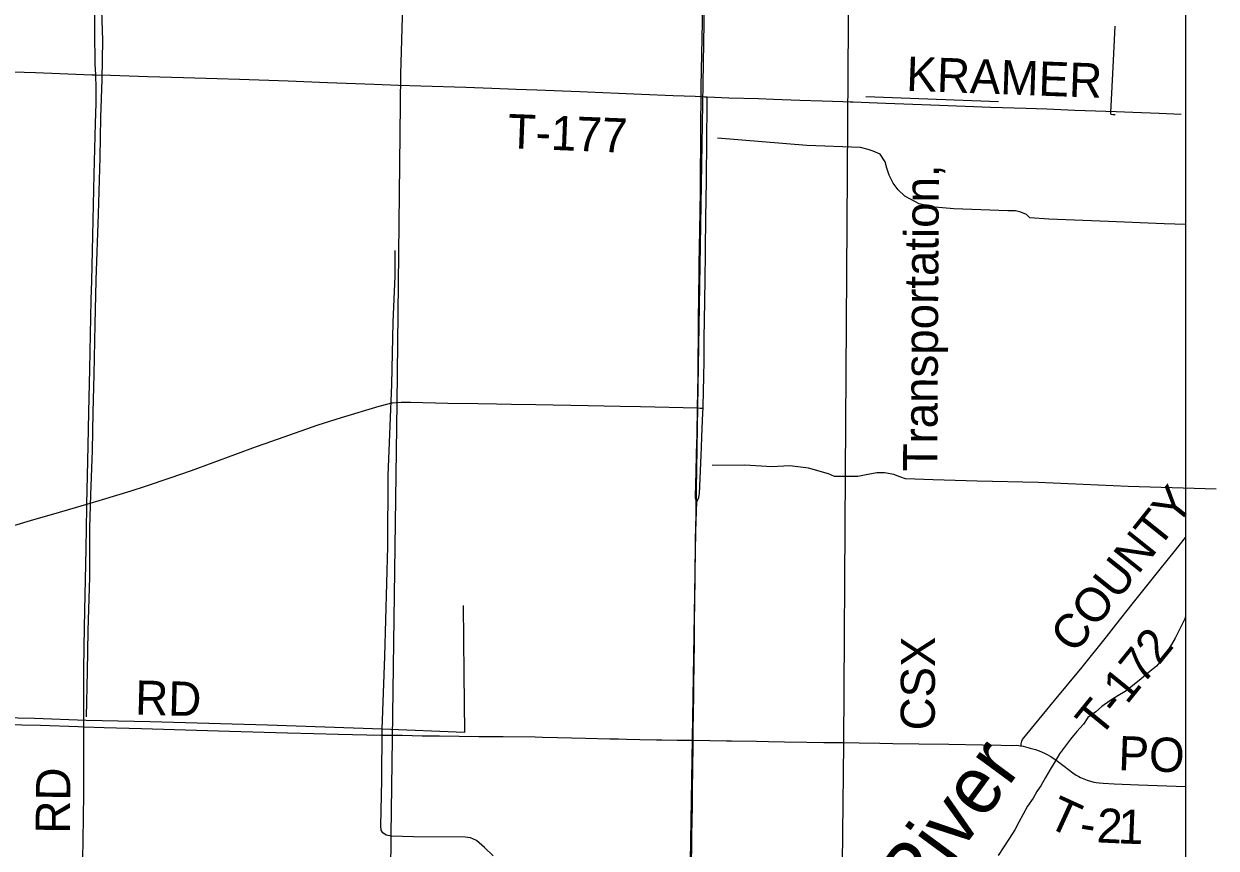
# Model space of a CAD drawing. Extents: x 0 to 680, y 0 to 834.
# Drawn here: x 300.6 to 376.6, y 223.2 to 275.7 of the extents above; entities that cross this region are included whole.
import ezdxf

# ---------------------------------------------------------------- set-up
doc = ezdxf.new("R2010")
doc.units = 0
for name, color, linetype in [('GM_X_Interstate_Route', 7, 'Continuous'), ('GM_X_Major_River', 7, 'Continuous'), ('GM_X_Minor_River', 7, 'Continuous'), ('GM_X_Minor_River_Text', 7, 'Continuous'), ('GM_X_Rail_Line', 7, 'Continuous'), ('GM_X_Rail_Line_Text', 7, 'Continuous'), ('GM_X_State_Route', 7, 'Continuous'), ('GM_X_Township_Road', 7, 'Continuous'), ('GM_X_Township_Road_Text', 7, 'Continuous')]:
    doc.layers.add(name, color=color, linetype=linetype)

msp = doc.modelspace()

# ---------------------------------------------------------------- linework, layer by layer
at = {"layer": 'GM_X_Interstate_Route'}
msp.add_lwpolyline([(44.693, 394.069), (374.693, 394.069), (374.693, 64.069), (44.693, 64.069)], close=True, dxfattribs=at)
at = {"layer": 'GM_X_Major_River'}
msp.add_lwpolyline([(374.693, 237.983), (374.631, 237.824), (374.411, 237.358), (374.22, 236.979), (374.015, 236.6), (373.795, 236.192), (373.502, 235.727), (373.268, 235.333), (372.844, 234.824), (372.304, 234.388), (371.851, 234.01), (371.31, 233.56), (370.843, 233.196), (370.376, 232.92), (369.85, 232.616), (369.339, 232.253), (368.974, 231.918), (368.463, 231.54), (368.17, 231.118), (367.746, 230.653), (367.351, 230.173), (366.971, 229.663), (366.649, 229.241), (366.356, 228.731), (366.063, 228.236), (365.756, 227.727), (365.462, 227.202), (365.199, 226.824), (364.965, 226.416), (364.613, 225.907), (364.335, 225.383), (364.056, 224.873), (363.793, 224.392), (363.471, 223.868), (363.105, 223.315), (362.739, 222.762)], dxfattribs=at)
at = {"layer": 'GM_X_Minor_River'}
for points in [[(305.442, 306.343), (305.457, 301.645), (305.341, 297.006), (305.374, 293.286), (305.384, 291.784), (305.402, 288.107), (305.459, 283.016), (305.518, 278.523), (305.638, 274.715), (305.601, 272.206), (305.506, 269.77), (305.455, 267.232), (305.357, 263.614), (305.213, 259.414), (305.146, 256.599), (305.078, 253.404), (305.027, 250.997), (304.976, 248.562), (304.88, 245.732), (304.8, 243.632), (304.805, 240.481), (304.707, 237.068), (304.655, 234.472), (304.603, 231.584)], [(362.755, 270.768), (354.305, 271.1)], [(374.693, 262.952), (373.324, 263.006), (369.784, 263.147), (365.967, 263.29), (364.758, 263.381), (364.554, 263.6), (364.191, 263.747), (363.841, 263.821), (363.36, 263.837), (359.922, 263.949), (358.702, 264.075), (357.709, 264.277), (356.792, 264.761), (356.356, 265.171), (356.052, 265.595), (355.791, 266.106), (355.632, 266.559), (355.531, 266.953), (355.212, 267.45), (354.776, 267.626), (354.441, 267.729), (353.961, 267.862), (350.537, 267.989), (344.856, 268.457)], [(328.75, 223.913), (325.458, 223.937), (324.059, 223.985), (323.724, 224.044), (323.506, 224.205), (323.405, 224.366), (323.376, 224.643), (323.444, 227.546), (323.468, 230.798), (323.629, 235.436), (323.825, 242.452), (323.853, 246.959), (323.98, 250.139), (324.075, 252.764), (324.16, 256.732), (324.286, 259.663), (324.291, 261.297)], [(376.638, 246.089), (371.029, 246.266), (365.289, 246.516), (361.399, 246.615), (358.587, 246.696), (356.839, 246.76), (356.461, 246.892), (356.097, 247.039), (355.5, 247.143), (355.005, 247.13), (354.319, 247), (353.795, 246.9), (353.052, 246.902), (352.308, 246.904), (351.916, 247.066), (350.649, 247.434), (349.455, 247.583), (348.304, 247.529), (346.585, 247.621), (344.501, 247.613)], [(328.622, 238.689), (328.666, 234.356), (328.713, 230.593), (323.468, 230.798), (316.155, 231.054), (308.681, 231.28), (304.588, 231.365), (301.295, 231.477), (296.079, 231.595), (294.448, 231.644), (284.73, 231.805), (279.515, 231.952), (273.848, 232.085), (267.511, 232.411), (265.69, 232.416)], [(330.553, 222.74), (329.987, 223.267), (329.478, 223.706), (329.108, 223.889), (328.75, 223.913)]]:
    msp.add_lwpolyline(points, dxfattribs=at)
at = {"layer": 'GM_X_Rail_Line'}
for points in [[(351.218, 64.069), (351.448, 90.121), (351.798, 116.184), (351.86, 139.423), (352.175, 154.252), (352.451, 189.912), (352.901, 229.863), (353.003, 247.107), (353.355, 298.069), (353.602, 311.675), (353.78, 316.856), (353.954, 319.076), (354.473, 323.516), (355.976, 338.772), (356.265, 341.847), (356.561, 344.985), (356.644, 347.076), (356.685, 349.146), (356.788, 357.395), (356.901, 372.817), (357.146, 391.252), (357.174, 394.069)], [(332.297, 358.476), (331.74, 334.991), (331.623, 332.119), (331.235, 330.489), (330.77, 329.441), (329.838, 328.432), (326.114, 325.676), (325.377, 324.318), (325.144, 323.27), (325.144, 290.084), (324.626, 272.539), (324.407, 251.582), (324.019, 224.102), (323.747, 191.887)], [(341.694, 64.069), (341.887, 75.733), (342.297, 152.995), (342.913, 209.384), (343.255, 230.188), (343.597, 251.334), (344.253, 291.298), (344.078, 319.736), (344.92, 358.256)]]:
    msp.add_lwpolyline(points, dxfattribs=at)
at = {"layer": 'GM_X_State_Route'}
msp.add_line((343.571, 251.27), (343.603, 253.33), dxfattribs=at)
for points in [[(343.805, 271.112), (343.813, 271.777), (343.881, 275.833), (343.936, 279.055), (343.938, 280.13), (343.944, 280.486), (343.969, 281.315), (343.992, 283.343), (343.995, 283.94), (344.039, 285.967), (344.048, 286.684), (344.048, 286.771)], [(343.603, 253.33), (343.606, 253.52), (343.609, 254.117), (343.637, 256.026), (343.628, 256.981), (343.658, 258.292), (343.676, 259.964), (343.685, 260.44), (343.723, 262.588), (343.752, 265.094), (343.783, 269.271), (343.805, 271.112)], [(343.977, 253.276), (343.996, 254.251), (344, 255.803), (344.019, 256.757), (344.04, 258.188), (344.052, 259.382), (344.074, 261.172), (344.11, 263.558), (344.127, 264.393), (344.134, 265.944), (344.188, 270.598), (344.195, 271.095)], [(343.914, 250.989), (343.926, 251.262), (343.93, 251.358), (343.977, 253.276)], [(343.533, 245.307), (343.599, 245.408), (343.658, 245.569), (343.682, 245.707), (343.693, 245.807), (343.822, 248.745), (343.844, 249.432), (343.914, 250.989)], [(343.543, 249.42), (343.546, 249.628), (343.571, 251.27)], [(343.533, 245.307), (343.473, 245.444), (343.45, 245.551), (343.439, 245.695), (343.464, 246.355), (343.536, 249.146), (343.543, 249.42)], [(343.377, 236.705), (343.385, 237.901), (343.389, 238.086), (343.397, 238.497), (343.407, 239.389), (343.413, 239.967), (343.417, 240.408), (343.427, 241.361), (343.434, 241.964), (343.442, 242.667), (343.451, 243.126), (343.459, 243.4), (343.533, 245.307)], [(343.335, 233.398), (343.356, 235.155), (343.371, 236.109), (343.376, 236.589), (343.377, 236.705)], [(343.294, 230.099), (343.304, 230.74), (343.317, 231.813), (343.33, 232.94), (343.335, 233.398)], [(343.215, 224.281), (343.222, 224.733), (343.244, 226.151), (343.255, 226.896), (343.26, 227.206), (343.272, 227.977), (343.294, 230.099)], [(343.155, 221.214), (343.18, 222.128), (343.203, 223.559), (343.212, 224.131), (343.215, 224.281)]]:
    msp.add_lwpolyline(points, dxfattribs=at)
at = {"layer": 'GM_X_Township_Road'}
for p, q in [((343.419, 271.128), (343.805, 271.112)), ((343.805, 271.112), (344.009, 271.103)), ((344.009, 271.103), (344.195, 271.095)), ((343.782, 251.265), (343.926, 251.262)), ((323.654, 230.421), (323.912, 230.421))]:
    msp.add_line(p, q, dxfattribs=at)
for points in [[(305.204, 272.497), (305.177, 273.206), (305.157, 275.236), (305.123, 282.638), (305.107, 285.503), (305.092, 287.653), (305.089, 290.16), (305.093, 290.578)], [(369.924, 269.984), (369.93, 270.106), (369.95, 270.508), (370.072, 272.99), (370.202, 275.594)], [(295.46, 272.836), (296.118, 272.813), (299.22, 272.711), (301.368, 272.639), (302.918, 272.587), (304.946, 272.504), (305.204, 272.497)], [(304.638, 245.148), (304.669, 246.95), (304.722, 248.86), (304.77, 251.008), (304.82, 253.753), (304.923, 258.17), (304.952, 259.363), (304.991, 261.273), (305.112, 266.167), (305.19, 269.389), (305.223, 270.701), (305.227, 271.775), (305.208, 272.37), (305.204, 272.497)], [(305.204, 272.497), (306.139, 272.47), (308.525, 272.39), (310.792, 272.326), (312.939, 272.268), (314.368, 272.213), (317.47, 272.105), (319.973, 272.012), (322.955, 271.901), (324.502, 271.836), (325.926, 271.794), (328.79, 271.703), (330.459, 271.642), (332.01, 271.589), (333.322, 271.536), (336.065, 271.424), (340, 271.255), (342.028, 271.186), (343.419, 271.128)], [(344.195, 271.095), (345.559, 271.033), (347.468, 270.979), (348.423, 270.944), (350.093, 270.881), (351.524, 270.844), (352.836, 270.792), (353.313, 270.774), (353.505, 270.767)], [(353.505, 270.767), (354.505, 270.733), (355.579, 270.7), (358.442, 270.579), (361.186, 270.485), (362.26, 270.443), (364.526, 270.369), (365.839, 270.326), (367.628, 270.245), (370.253, 270.154), (371.326, 270.112), (372.996, 270.048), (374.415, 269.984)], [(369.924, 269.984), (370.056, 269.978), (370.202, 269.974)], [(324.117, 251.593), (324.348, 251.622), (324.671, 251.638), (325.269, 251.63), (327.655, 251.583), (329.565, 251.565), (330.758, 251.54), (331.712, 251.52), (333.263, 251.489), (336.604, 251.423), (338.633, 251.381), (339.945, 251.358), (343.571, 251.27)], [(304.638, 245.148), (305.632, 245.437), (307.461, 245.987), (308.369, 246.28), (309.949, 246.823), (311.3, 247.296), (315.449, 248.809), (316.013, 249.003), (317.586, 249.567), (318.598, 249.926), (319.39, 250.192), (320.87, 250.657), (323.272, 251.375), (323.846, 251.538), (324.079, 251.588), (324.117, 251.593)], [(343.571, 251.27), (343.733, 251.266), (343.782, 251.265)], [(299.563, 243.655), (301.051, 244.095), (302.885, 244.626), (303.913, 244.937), (304.638, 245.148)], [(304.447, 230.956), (304.437, 233.103), (304.454, 234.536), (304.474, 236.087), (304.507, 238.356), (304.586, 242.295), (304.635, 244.921), (304.638, 245.148)], [(364.198, 229.744), (364.205, 229.874), (364.219, 229.956), (364.243, 230.042), (364.294, 230.147), (364.366, 230.242), (365.046, 231.071), (366.341, 232.632), (368.088, 234.747), (369.657, 236.698), (370.245, 237.449), (371.275, 238.764), (373.067, 240.995), (373.964, 242.111), (374.693, 243.025)], [(265.433, 232.122), (265.794, 232.108), (274.977, 231.829), (280.224, 231.656), (282.371, 231.608), (287.142, 231.477), (289.05, 231.423), (291.077, 231.358), (293.82, 231.268), (296.086, 231.201), (297.398, 231.173), (299.544, 231.107), (300.499, 231.082), (301.691, 231.053), (304.076, 230.967), (304.447, 230.956)], [(304.165, 192.233), (304.146, 192.388), (304.122, 192.576), (304.105, 192.748), (304.089, 192.99), (304.093, 193.588), (304.119, 195.14), (304.138, 197.408), (304.152, 199.438), (304.171, 201.348), (304.185, 202.9), (304.2, 204.213), (304.213, 206.72), (304.222, 208.152), (304.237, 210.182), (304.281, 213.882), (304.303, 215.912), (304.33, 217.822), (304.351, 219.374), (304.389, 222.478), (304.423, 225.104), (304.437, 226.775), (304.453, 229.521), (304.447, 230.956)], [(304.447, 230.956), (305.745, 230.918), (308.131, 230.855), (313.735, 230.682), (317.433, 230.575), (319.102, 230.522), (320.653, 230.484), (323.397, 230.421), (323.654, 230.421)], [(323.912, 230.421), (324.741, 230.414), (326.011, 230.39)], [(326.011, 230.39), (327.128, 230.37), (329.635, 230.338), (331.186, 230.33), (333.215, 230.306), (333.691, 230.292), (334.64, 230.272), (336.428, 230.23), (337.979, 230.194), (338.528, 230.18)], [(338.528, 230.18), (339.052, 230.166), (339.888, 230.151), (340.953, 230.132)], [(340.953, 230.132), (341.294, 230.126), (342.275, 230.109), (343.294, 230.099)], [(343.294, 230.099), (345.426, 230.062), (345.734, 230.057)], [(345.734, 230.057), (347.331, 230.03), (348.105, 230.018)], [(348.105, 230.018), (349.118, 230.001), (350.547, 229.98), (351.619, 229.965), (352.81, 229.949), (353.88, 229.936), (355.19, 229.902), (356.024, 229.891), (357.691, 229.871), (359.597, 229.845), (361.741, 229.816), (362.931, 229.786), (363.653, 229.773)], [(363.653, 229.773), (363.882, 229.776), (364.053, 229.763), (364.162, 229.749), (364.198, 229.744)], [(364.198, 229.744), (364.329, 229.722), (364.474, 229.688), (364.771, 229.603), (365.117, 229.501), (365.455, 229.376), (365.784, 229.228), (366.1, 229.054), (366.434, 228.823), (366.946, 228.438), (367.496, 228.021), (367.711, 227.873), (367.873, 227.783), (367.989, 227.724), (368.197, 227.636), (368.406, 227.554), (368.617, 227.494), (368.845, 227.433), (368.982, 227.408), (369.176, 227.382), (369.431, 227.358), (370.145, 227.319), (371.696, 227.26), (374.693, 227.142)]]:
    msp.add_lwpolyline(points, dxfattribs=at)

# ---------------------------------------------------------------- texts
at = {"layer": 'GM_X_Minor_River_Text'}
msp.add_text('River', height=3.6383, rotation=53.62845, dxfattribs=at).set_placement((357.614, 219.268))
at = {"layer": 'GM_X_Rail_Line_Text'}
for s, height, rotation, p in [('Transportation,', 2.17455, 89.66381, (358.85, 247.226)), ('CSX', 2.1745, 89.73488, (358.694, 230.722))]:
    msp.add_text(s, height=height, rotation=rotation, dxfattribs=at).set_placement(p)
at = {"layer": 'GM_X_Township_Road_Text'}
for s, height, rotation, p in [('KRAMER', 2.1818, 357.92007, (356.858, 271.483)), ('T-177', 2.1818, 357.75434, (331.439, 267.828)), ('COUNTY', 2.1818, 51.41746, (367.611, 235.538)), ('T-172', 2.1818, 50.94582, (369.211, 230.182)), ('RD', 2.1818, 358.51937, (307.699, 231.734)), ('PO', 2.1818, 357.92854, (370.376, 228.194)), ('RD', 2.1818, 89.50829, (303.554, 224.137)), ('T', 2.182, 335.45744, (365.746, 224.632)), ('2', 2.182, 357.2918, (368.99, 223.598)), ('1', 2.182, 357.76643, (370.352, 223.534)), ('-', 2.182, 350.76945, (367.837, 223.77))]:
    msp.add_text(s, height=height, rotation=rotation, dxfattribs=at).set_placement(p)

doc.saveas('drawing.dxf')
